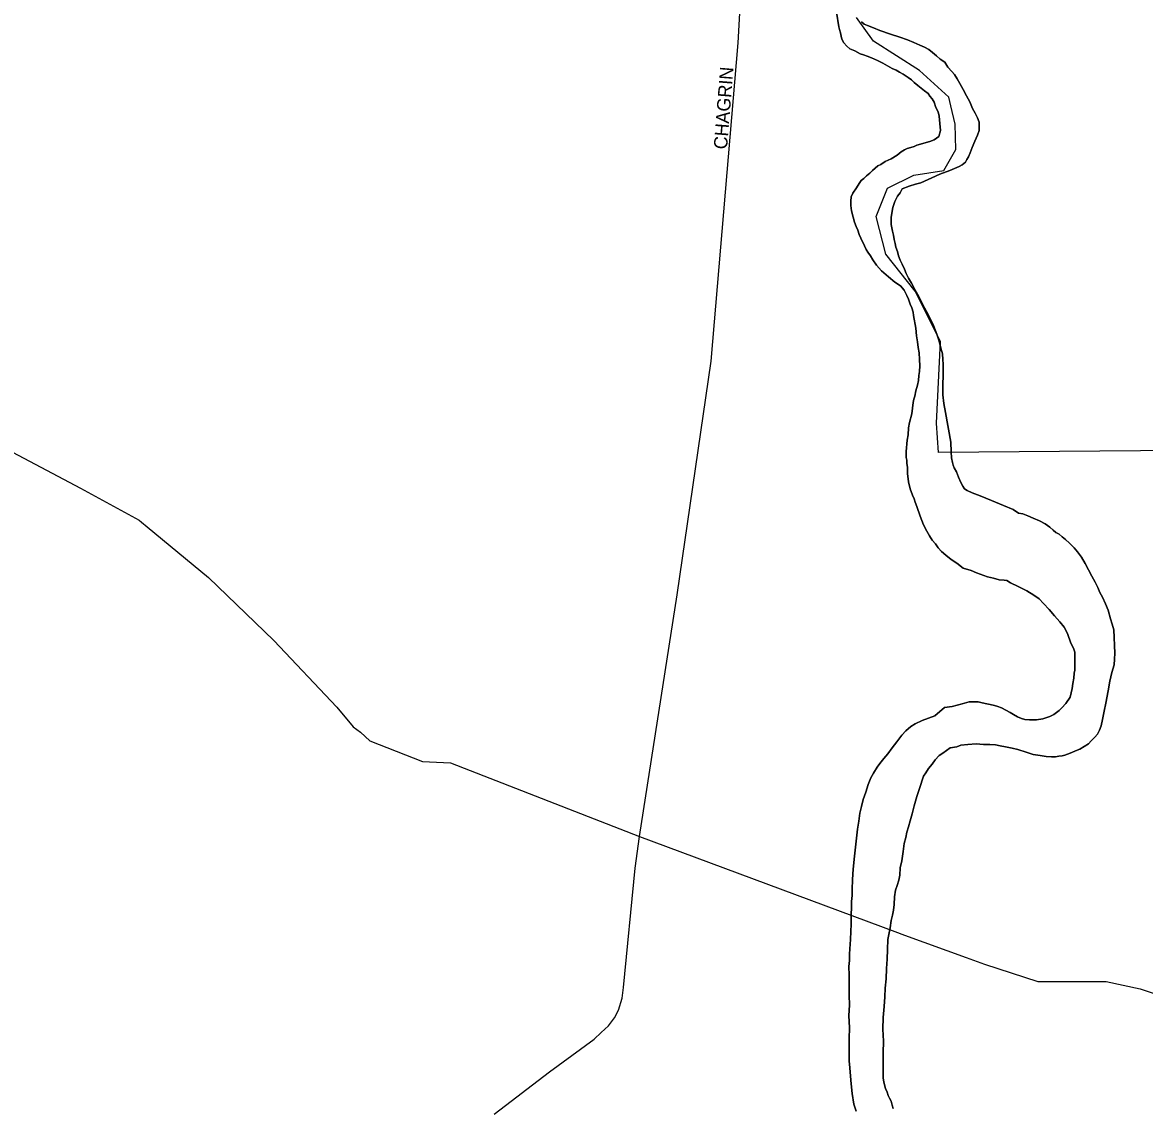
# Model space of a CAD drawing. Extents: x -561 to 1170, y 0 to 846.
# Drawn here: x 445.86 to 457.18, y 230.31 to 241.23 of the extents above; entities that cross this region are included whole.
import ezdxf

# ---------------------------------------------------------------- set-up
doc = ezdxf.new("R2010")
doc.units = 0
for name, color, linetype in [('GM_X_City_Street', 7, 'Continuous'), ('GM_X_City_Street_Text', 7, 'Continuous'), ('GM_X_Major_River', 7, 'Continuous'), ('GM_X_Township', 7, 'Continuous')]:
    doc.layers.add(name, color=color, linetype=linetype)

msp = doc.modelspace()

# ---------------------------------------------------------------- linework, layer by layer
at = {"layer": 'GM_X_City_Street'}
for points in [[(423.168, 249.12), (423.399, 248.99), (424.595, 248.367), (426.243, 247.517), (427.255, 246.919), (427.858, 246.587), (430.367, 245.244), (435.214, 242.618), (440.698, 239.665), (444.397, 237.625), (446.448, 236.537), (447.041, 236.215), (447.063, 236.196), (447.121, 236.148)], [(450.619, 230.227), (451.178, 230.656), (451.628, 230.985), (451.699, 231.052), (451.771, 231.12), (451.832, 231.201), (451.872, 231.277), (451.909, 231.398), (451.925, 231.505), (452.043, 232.707), (452.085, 233.028), (452.465, 235.463), (452.807, 237.82), (453.079, 241.027), (453.253, 244.099)], [(447.121, 236.148), (447.74, 235.639), (448.397, 235.004), (449.032, 234.33), (449.197, 234.132), (449.273, 234.079), (449.366, 233.993), (449.898, 233.784), (450.178, 233.769), (452.085, 233.028), (454.661, 232.068), (454.756, 232.034)], [(454.756, 232.034), (455.378, 231.806), (455.564, 231.74), (456.101, 231.566), (456.436, 231.565), (456.792, 231.564), (457.133, 231.493), (457.507, 231.369), (457.82, 231.108), (457.922, 230.996), (458.125, 230.773), (458.377, 230.511), (458.46, 230.398), (458.489, 230.353)]]:
    msp.add_lwpolyline(points, dxfattribs=at)
at = {"layer": 'GM_X_Major_River'}
for points in [[(454.073, 241.335), (454.096, 241.188), (454.102, 241.161), (454.113, 241.129), (454.118, 241.096), (454.124, 241.064), (454.146, 241.026), (454.174, 240.994), (454.206, 240.967), (454.255, 240.945), (454.31, 240.918), (454.342, 240.908), (454.38, 240.892), (454.424, 240.876), (454.484, 240.849), (454.538, 240.822), (454.587, 240.796), (454.631, 240.769), (454.674, 240.753), (454.707, 240.731), (454.745, 240.71), (454.794, 240.678), (454.827, 240.656), (454.854, 240.629), (454.893, 240.597), (454.925, 240.57), (454.958, 240.543), (454.996, 240.516), (455.013, 240.489), (455.035, 240.462), (455.057, 240.43), (455.074, 240.376), (455.096, 240.332), (455.107, 240.289), (455.113, 240.213), (455.119, 240.143), (455.103, 240.083), (455.055, 240.05), (455.012, 240.033), (454.882, 239.995)], [(454.882, 239.995), (455.012, 240.033), (455.055, 240.05), (455.103, 240.083), (455.119, 240.143), (455.113, 240.213), (455.107, 240.289), (455.096, 240.332), (455.074, 240.376), (455.057, 240.43), (455.035, 240.462), (455.013, 240.489), (454.996, 240.516), (454.958, 240.543), (454.925, 240.57), (454.893, 240.597), (454.854, 240.629), (454.827, 240.656), (454.794, 240.678), (454.745, 240.71), (454.707, 240.731), (454.674, 240.753), (454.631, 240.769), (454.587, 240.796), (454.538, 240.822), (454.484, 240.849), (454.424, 240.876), (454.38, 240.892), (454.342, 240.908), (454.31, 240.918), (454.255, 240.945), (454.206, 240.967), (454.174, 240.994), (454.146, 241.026), (454.124, 241.064), (454.118, 241.096), (454.113, 241.129), (454.102, 241.161), (454.096, 241.188), (454.073, 241.335)], [(454.804, 239.582), (454.869, 239.604), (454.923, 239.615), (455.031, 239.665), (455.112, 239.703), (455.215, 239.742), (455.307, 239.78), (455.339, 239.797), (455.371, 239.824), (455.387, 239.851), (455.403, 239.879), (455.419, 239.917), (455.44, 239.971), (455.467, 240.036), (455.493, 240.096), (455.509, 240.145), (455.509, 240.189), (455.509, 240.227), (455.492, 240.27), (455.47, 240.318), (455.442, 240.367), (455.415, 240.432), (455.382, 240.492), (455.348, 240.556), (455.315, 240.616), (455.288, 240.665), (455.26, 240.708), (455.233, 240.74), (455.195, 240.783), (455.162, 240.832), (455.118, 240.864), (455.08, 240.896), (455.041, 240.929), (455.003, 240.961), (454.96, 240.982), (454.911, 241.004), (454.851, 241.031), (454.786, 241.057), (454.709, 241.084), (454.617, 241.116), (454.508, 241.153), (454.443, 241.18), (454.383, 241.201), (454.35, 241.217), (454.323, 241.239)], [(454.323, 241.239), (454.35, 241.217), (454.383, 241.201), (454.443, 241.18), (454.508, 241.153), (454.617, 241.116), (454.709, 241.084), (454.786, 241.057), (454.851, 241.031), (454.911, 241.004), (454.96, 240.982), (455.003, 240.961), (455.041, 240.929), (455.08, 240.896), (455.118, 240.864), (455.162, 240.832), (455.195, 240.783), (455.233, 240.74), (455.26, 240.708), (455.288, 240.665), (455.315, 240.616), (455.348, 240.556), (455.382, 240.492), (455.415, 240.432), (455.442, 240.367), (455.47, 240.318), (455.492, 240.27), (455.509, 240.227), (455.509, 240.189), (455.509, 240.145), (455.493, 240.096), (455.467, 240.036), (455.44, 239.971), (455.419, 239.917), (455.403, 239.879), (455.387, 239.851), (455.371, 239.824), (455.339, 239.797), (455.307, 239.78), (455.215, 239.742), (455.112, 239.703), (455.031, 239.665), (454.923, 239.615), (454.869, 239.604), (454.804, 239.582)], [(454.882, 239.995), (454.855, 239.983), (454.822, 239.972), (454.785, 239.961), (454.758, 239.95), (454.725, 239.928), (454.682, 239.896), (454.623, 239.857), (454.563, 239.83), (454.52, 239.802), (454.488, 239.786), (454.461, 239.764), (454.434, 239.742), (454.407, 239.715), (454.375, 239.687), (454.348, 239.66), (454.321, 239.638), (454.3, 239.611), (454.273, 239.567), (454.236, 239.513), (454.22, 239.475), (454.215, 239.431), (454.215, 239.388), (454.221, 239.334), (454.238, 239.269), (454.254, 239.22), (454.271, 239.177), (454.288, 239.139), (454.299, 239.096), (454.316, 239.058), (454.354, 238.982), (454.371, 238.944), (454.387, 238.917), (454.415, 238.879), (454.437, 238.841), (454.475, 238.787), (454.524, 238.728), (454.596, 238.669), (454.661, 238.615), (454.716, 238.577), (454.754, 238.534), (454.782, 238.48), (454.798, 238.442), (454.815, 238.394), (454.831, 238.356), (454.843, 238.312), (454.848, 238.28), (454.871, 238.15), (454.877, 238.074), (454.889, 238.014), (454.895, 237.955), (454.906, 237.901), (454.907, 237.835), (454.913, 237.77), (454.908, 237.716), (454.903, 237.673), (454.898, 237.624), (454.887, 237.575), (454.871, 237.521), (454.861, 237.466), (454.851, 237.434), (454.845, 237.401), (454.83, 237.287), (454.809, 237.2), (454.799, 237.146), (454.794, 237.075), (454.784, 237.021), (454.774, 236.907), (454.774, 236.847), (454.78, 236.82), (454.78, 236.788), (454.786, 236.75), (454.787, 236.685), (454.798, 236.603), (454.815, 236.533), (454.837, 236.468), (454.854, 236.43), (454.865, 236.398), (454.882, 236.354), (454.915, 236.257), (454.949, 236.17), (454.982, 236.105), (455.009, 236.057), (455.037, 236.013), (455.07, 235.976), (455.097, 235.938), (455.13, 235.9), (455.174, 235.862), (455.228, 235.819), (455.283, 235.782), (455.348, 235.733), (455.43, 235.707), (455.484, 235.685), (455.593, 235.643), (455.653, 235.632), (455.712, 235.616), (455.761, 235.611), (455.789, 235.606), (455.827, 235.585)], [(455.827, 235.585), (455.789, 235.606), (455.761, 235.611), (455.712, 235.616), (455.653, 235.632), (455.593, 235.643), (455.484, 235.685), (455.43, 235.707), (455.348, 235.733), (455.283, 235.782), (455.228, 235.819), (455.174, 235.862), (455.13, 235.9), (455.097, 235.938), (455.07, 235.976), (455.037, 236.013), (455.009, 236.057), (454.982, 236.105), (454.949, 236.17), (454.915, 236.257), (454.882, 236.354), (454.865, 236.398), (454.854, 236.43), (454.837, 236.468), (454.815, 236.533), (454.798, 236.603), (454.787, 236.685), (454.786, 236.75), (454.78, 236.788), (454.78, 236.82), (454.774, 236.847), (454.774, 236.907), (454.784, 237.021), (454.794, 237.075), (454.799, 237.146), (454.809, 237.2), (454.83, 237.287), (454.845, 237.401), (454.851, 237.434), (454.861, 237.466), (454.871, 237.521), (454.887, 237.575), (454.898, 237.624), (454.903, 237.673), (454.908, 237.716), (454.913, 237.77), (454.907, 237.835), (454.906, 237.901), (454.895, 237.955), (454.889, 238.014), (454.877, 238.074), (454.871, 238.15), (454.848, 238.28), (454.843, 238.312), (454.831, 238.356), (454.815, 238.394), (454.798, 238.442), (454.782, 238.48), (454.754, 238.534), (454.716, 238.577), (454.661, 238.615), (454.596, 238.669), (454.524, 238.728), (454.475, 238.787), (454.437, 238.841), (454.415, 238.879), (454.387, 238.917), (454.371, 238.944), (454.354, 238.982), (454.316, 239.058), (454.299, 239.096), (454.288, 239.139), (454.271, 239.177), (454.254, 239.22), (454.238, 239.269), (454.221, 239.334), (454.215, 239.388), (454.215, 239.431), (454.22, 239.475), (454.236, 239.513), (454.273, 239.567), (454.3, 239.611), (454.321, 239.638), (454.348, 239.66), (454.375, 239.687), (454.407, 239.715), (454.434, 239.742), (454.461, 239.764), (454.488, 239.786), (454.52, 239.802), (454.563, 239.83), (454.623, 239.857), (454.682, 239.896), (454.725, 239.928), (454.758, 239.95), (454.785, 239.961), (454.822, 239.972), (454.855, 239.983), (454.882, 239.995)], [(456.702, 234.06), (456.724, 234.099), (456.739, 234.142), (456.755, 234.207), (456.771, 234.289), (456.786, 234.37), (456.812, 234.495), (456.828, 234.593), (456.848, 234.68), (456.87, 234.756), (456.874, 234.816), (456.879, 234.875), (456.866, 235.109), (456.85, 235.168), (456.833, 235.222), (456.81, 235.309), (456.783, 235.374), (456.755, 235.439), (456.727, 235.487), (456.705, 235.536), (456.678, 235.59), (456.645, 235.65), (456.612, 235.715), (456.578, 235.779), (456.54, 235.844), (456.501, 235.898), (456.469, 235.936), (456.419, 235.985), (456.381, 236.022), (456.348, 236.049), (456.316, 236.076), (456.283, 236.092), (456.256, 236.114), (456.223, 236.146), (456.174, 236.178), (456.119, 236.21), (456.054, 236.237), (455.999, 236.258), (455.951, 236.28), (455.907, 236.285), (455.853, 236.323), (455.755, 236.365), (455.635, 236.413), (455.521, 236.461), (455.439, 236.493), (455.39, 236.515), (455.363, 236.531), (455.346, 236.558), (455.324, 236.596), (455.302, 236.65), (455.28, 236.704), (455.258, 236.742), (455.247, 236.769), (455.241, 236.796), (455.23, 236.845), (455.229, 236.904), (455.223, 237.002), (455.172, 237.3), (455.154, 237.392), (455.143, 237.479), (455.142, 237.544), (455.142, 237.604), (455.147, 237.653), (455.146, 237.696), (455.146, 237.745), (455.146, 237.788), (455.145, 237.837), (455.139, 237.891), (455.122, 237.951), (455.105, 238.021), (455.083, 238.092), (455.05, 238.178), (455.011, 238.254), (454.978, 238.319), (454.939, 238.394), (454.901, 238.47), (454.862, 238.54), (454.829, 238.605), (454.796, 238.654), (454.774, 238.703), (454.757, 238.746), (454.735, 238.795), (454.713, 238.838), (454.697, 238.881), (454.685, 238.924), (454.669, 238.968), (454.663, 239.006), (454.652, 239.044), (454.646, 239.087), (454.635, 239.13), (454.629, 239.163), (454.623, 239.195), (454.623, 239.233), (454.623, 239.266), (454.628, 239.309), (454.638, 239.369), (454.659, 239.429), (454.686, 239.483), (454.713, 239.516), (454.734, 239.554), (454.804, 239.582)], [(454.804, 239.582), (454.734, 239.554), (454.713, 239.516), (454.686, 239.483), (454.659, 239.429), (454.638, 239.369), (454.628, 239.309), (454.623, 239.266), (454.623, 239.233), (454.623, 239.195), (454.629, 239.163), (454.635, 239.13), (454.646, 239.087), (454.652, 239.044), (454.663, 239.006), (454.669, 238.968), (454.685, 238.924), (454.697, 238.881), (454.713, 238.838), (454.735, 238.795), (454.757, 238.746), (454.774, 238.703), (454.796, 238.654), (454.829, 238.605), (454.862, 238.54), (454.901, 238.47), (454.939, 238.394), (454.978, 238.319), (455.011, 238.254), (455.05, 238.178), (455.083, 238.092), (455.105, 238.021), (455.122, 237.951), (455.139, 237.891), (455.145, 237.837), (455.146, 237.788), (455.146, 237.745), (455.146, 237.696), (455.147, 237.653), (455.142, 237.604), (455.142, 237.544), (455.143, 237.479), (455.154, 237.392), (455.172, 237.3), (455.223, 237.002), (455.229, 236.904), (455.23, 236.845), (455.241, 236.796), (455.247, 236.769), (455.258, 236.742), (455.28, 236.704), (455.302, 236.65), (455.324, 236.596), (455.346, 236.558), (455.363, 236.531), (455.39, 236.515), (455.439, 236.493), (455.521, 236.461), (455.635, 236.413), (455.755, 236.365), (455.853, 236.323), (455.907, 236.285), (455.951, 236.28), (455.999, 236.258), (456.054, 236.237), (456.119, 236.21), (456.174, 236.178), (456.223, 236.146), (456.256, 236.114), (456.283, 236.092), (456.316, 236.076), (456.348, 236.049), (456.381, 236.022), (456.419, 235.985), (456.469, 235.936), (456.501, 235.898), (456.54, 235.844), (456.578, 235.779), (456.612, 235.715), (456.645, 235.65), (456.678, 235.59), (456.705, 235.536), (456.727, 235.487), (456.755, 235.439), (456.783, 235.374), (456.81, 235.309), (456.833, 235.222), (456.85, 235.168), (456.866, 235.109), (456.879, 234.875), (456.874, 234.816), (456.87, 234.756), (456.848, 234.68), (456.828, 234.593), (456.812, 234.495), (456.786, 234.37), (456.771, 234.289), (456.755, 234.207), (456.739, 234.142), (456.724, 234.099), (456.702, 234.06)], [(455.827, 235.585), (455.903, 235.547), (455.99, 235.504), (456.061, 235.461), (456.115, 235.424), (456.159, 235.375), (456.214, 235.316), (456.269, 235.251), (456.323, 235.192), (456.367, 235.138), (456.4, 235.073), (456.434, 234.976), (456.461, 234.927), (456.473, 234.884), (456.473, 234.84), (456.473, 234.786), (456.474, 234.759), (456.474, 234.705), (456.469, 234.672), (456.464, 234.623), (456.454, 234.569), (456.449, 234.52), (456.428, 234.433), (456.385, 234.368), (456.342, 234.324), (456.315, 234.297), (456.261, 234.258), (456.224, 234.236), (456.153, 234.214), (456.088, 234.203), (456.018, 234.202), (455.969, 234.208), (455.936, 234.218), (455.898, 234.234), (455.855, 234.256), (455.822, 234.277), (455.735, 234.325), (455.697, 234.336), (455.664, 234.347), (455.621, 234.357), (455.572, 234.368), (455.528, 234.378), (455.501, 234.383), (455.442, 234.383), (455.409, 234.383), (455.339, 234.366), (455.236, 234.338), (455.16, 234.327), (455.063, 234.245), (454.934, 234.195), (454.864, 234.162), (454.82, 234.135), (454.772, 234.091), (454.729, 234.048), (454.681, 233.982), (454.633, 233.922), (454.59, 233.862), (454.547, 233.813), (454.509, 233.764), (454.483, 233.726), (454.445, 233.666), (454.419, 233.617), (454.392, 233.552), (454.366, 233.475), (454.339, 233.399), (454.324, 233.329), (454.308, 233.263), (454.298, 233.182), (454.282, 233.101), (454.252, 232.829), (454.242, 232.731), (454.237, 232.655), (454.233, 232.585), (454.228, 232.503), (454.229, 232.433), (454.224, 232.373), (454.224, 232.314), (454.22, 232.238), (454.22, 232.145), (454.216, 232.069), (454.211, 231.988), (454.206, 231.896), (454.201, 231.841), (454.202, 231.776), (454.197, 231.717), (454.198, 231.63), (454.199, 231.532), (454.2, 231.429), (454.201, 231.326), (454.196, 231.223), (454.203, 231.098), (454.198, 230.99), (454.199, 230.876), (454.2, 230.821), (454.2, 230.767), (454.206, 230.697), (454.212, 230.61), (454.219, 230.534), (454.23, 230.436), (454.247, 230.328), (454.27, 230.258)], [(454.27, 230.258), (454.247, 230.328), (454.23, 230.436), (454.219, 230.534), (454.212, 230.61), (454.206, 230.697), (454.2, 230.767), (454.2, 230.821), (454.199, 230.876), (454.198, 230.99), (454.203, 231.098), (454.196, 231.223), (454.201, 231.326), (454.2, 231.429), (454.199, 231.532), (454.198, 231.63), (454.197, 231.717), (454.202, 231.776), (454.201, 231.841), (454.206, 231.896), (454.211, 231.988), (454.216, 232.069), (454.22, 232.145), (454.22, 232.238), (454.224, 232.314), (454.224, 232.373), (454.229, 232.433), (454.228, 232.503), (454.233, 232.585), (454.237, 232.655), (454.242, 232.731), (454.252, 232.829), (454.282, 233.101), (454.298, 233.182), (454.308, 233.263), (454.324, 233.329), (454.339, 233.399), (454.366, 233.475), (454.392, 233.552), (454.419, 233.617), (454.445, 233.666), (454.483, 233.726), (454.509, 233.764), (454.547, 233.813), (454.59, 233.862), (454.633, 233.922), (454.681, 233.982), (454.729, 234.048), (454.772, 234.091), (454.82, 234.135), (454.864, 234.162), (454.934, 234.195), (455.063, 234.245), (455.16, 234.327), (455.236, 234.338), (455.339, 234.366), (455.409, 234.383), (455.442, 234.383), (455.501, 234.383), (455.528, 234.378), (455.572, 234.368), (455.621, 234.357), (455.664, 234.347), (455.697, 234.336), (455.735, 234.325), (455.822, 234.277), (455.855, 234.256), (455.898, 234.234), (455.936, 234.218), (455.969, 234.208), (456.018, 234.202), (456.088, 234.203), (456.153, 234.214), (456.224, 234.236), (456.261, 234.258), (456.315, 234.297), (456.342, 234.324), (456.385, 234.368), (456.428, 234.433), (456.449, 234.52), (456.454, 234.569), (456.464, 234.623), (456.469, 234.672), (456.474, 234.705), (456.474, 234.759), (456.473, 234.786), (456.473, 234.84), (456.473, 234.884), (456.461, 234.927), (456.434, 234.976), (456.4, 235.073), (456.367, 235.138), (456.323, 235.192), (456.269, 235.251), (456.214, 235.316), (456.159, 235.375), (456.115, 235.424), (456.061, 235.461), (455.99, 235.504), (455.903, 235.547), (455.827, 235.585)], [(454.644, 230.287), (454.632, 230.32), (454.621, 230.358), (454.605, 230.39), (454.594, 230.417), (454.582, 230.45), (454.566, 230.488), (454.555, 230.525), (454.549, 230.553), (454.543, 230.59), (454.543, 230.645), (454.542, 230.715), (454.541, 230.845), (454.545, 230.965), (454.539, 231.084), (454.543, 231.203), (454.553, 231.312), (454.558, 231.41), (454.562, 231.497), (454.572, 231.594), (454.577, 231.697), (454.581, 231.79), (454.586, 231.887), (454.59, 231.99), (454.611, 232.105), (454.621, 232.181), (454.637, 232.235), (454.647, 232.284), (454.652, 232.343), (454.657, 232.419), (454.667, 232.485), (454.683, 232.534), (454.699, 232.588), (454.709, 232.637), (454.714, 232.713), (454.73, 232.783), (454.745, 232.876), (454.755, 232.957), (454.771, 233.017), (454.781, 233.071), (454.797, 233.126), (454.813, 233.185), (454.834, 233.256), (454.855, 233.338), (454.881, 233.43), (454.907, 233.512), (454.95, 233.637), (454.971, 233.669), (454.998, 233.713), (455.035, 233.757), (455.067, 233.8), (455.105, 233.844), (455.143, 233.866), (455.18, 233.893), (455.218, 233.92), (455.283, 233.932), (455.326, 233.948), (455.397, 233.954), (455.478, 233.96), (455.554, 233.955), (455.619, 233.956), (455.673, 233.951), (455.722, 233.94), (455.776, 233.93), (455.842, 233.919), (455.901, 233.903), (455.983, 233.877), (456.054, 233.855), (456.124, 233.845), (456.184, 233.835), (456.238, 233.83), (456.281, 233.83), (456.314, 233.836), (456.346, 233.841), (456.373, 233.847), (456.401, 233.858), (456.444, 233.874), (456.482, 233.891), (456.525, 233.907), (456.568, 233.935), (456.611, 233.962), (456.638, 233.99), (456.675, 234.028), (456.702, 234.06)], [(456.702, 234.06), (456.675, 234.028), (456.638, 233.99), (456.611, 233.962), (456.568, 233.935), (456.525, 233.907), (456.482, 233.891), (456.444, 233.874), (456.401, 233.858), (456.373, 233.847), (456.346, 233.841), (456.314, 233.836), (456.281, 233.83), (456.238, 233.83), (456.184, 233.835), (456.124, 233.845), (456.054, 233.855), (455.983, 233.877), (455.901, 233.903), (455.842, 233.919), (455.776, 233.93), (455.722, 233.94), (455.673, 233.951), (455.619, 233.956), (455.554, 233.955), (455.478, 233.96), (455.397, 233.954), (455.326, 233.948), (455.283, 233.932), (455.218, 233.92), (455.18, 233.893), (455.143, 233.866), (455.105, 233.844), (455.067, 233.8), (455.035, 233.757), (454.998, 233.713), (454.971, 233.669), (454.95, 233.637), (454.907, 233.512), (454.881, 233.43), (454.855, 233.338), (454.834, 233.256), (454.813, 233.185), (454.797, 233.126), (454.781, 233.071), (454.771, 233.017), (454.755, 232.957), (454.745, 232.876), (454.73, 232.783), (454.714, 232.713), (454.709, 232.637), (454.699, 232.588), (454.683, 232.534), (454.667, 232.485), (454.657, 232.419), (454.652, 232.343), (454.647, 232.284), (454.637, 232.235), (454.621, 232.181), (454.611, 232.105), (454.59, 231.99), (454.586, 231.887), (454.581, 231.79), (454.577, 231.697), (454.572, 231.594), (454.562, 231.497), (454.558, 231.41), (454.553, 231.312), (454.543, 231.203), (454.539, 231.084), (454.545, 230.965), (454.541, 230.845), (454.542, 230.715), (454.543, 230.645), (454.543, 230.59), (454.549, 230.553), (454.555, 230.525), (454.566, 230.488), (454.582, 230.45), (454.594, 230.417), (454.605, 230.39), (454.621, 230.358), (454.632, 230.32), (454.644, 230.287)]]:
    msp.add_lwpolyline(points, dxfattribs=at)
at = {"layer": 'GM_X_Township'}
msp.add_lwpolyline([(458.763, 236.929), (455.101, 236.899), (455.079, 237.195), (455.119, 238.018), (454.865, 238.523), (454.569, 238.896), (454.472, 239.276), (454.586, 239.563), (454.852, 239.693), (455.155, 239.741), (455.275, 239.952), (455.269, 240.207), (455.225, 240.391), (455.205, 240.478), (454.907, 240.75), (454.446, 241.044), (454.273, 241.282)], dxfattribs=at)

# ---------------------------------------------------------------- texts
at = {"layer": 'GM_X_City_Street_Text'}
msp.add_text('CHAGRIN', height=0.135, rotation=85.4612, dxfattribs=at).set_placement((452.967, 239.95))

doc.saveas('drawing.dxf')
